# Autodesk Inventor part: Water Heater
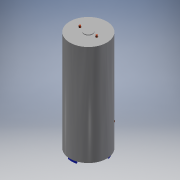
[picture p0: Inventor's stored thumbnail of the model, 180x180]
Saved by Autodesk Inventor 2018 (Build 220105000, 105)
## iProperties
flow_configuration: 1
height: 0 in
loss_method: 0
radius: 2.500 in
shape: 1 ul
width: 0 in
allow_slope_adjustment: 0
flow_configuration2: 1
flow_direction: 2
radius: 0.500 in
shape: 0 ul
Created: 2006-02
Part Number: Water Heater
Document SubType Name: Modeling
Designer: Autodesk, Inc.
Description: BODY - WATER HEATER, 45 GAL
Mass: 2.9406e+06 g
Surface Area: 32761.1 cm^2
Volume: 374598 cm^3
Density: 7.85 g/cm^3
Material: Galvanized Steel
Appearance: Steel
Title: BODY - WATER HEATER, 45 GAL
Author: Autodesk, Inc.
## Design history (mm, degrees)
sketch "Sketch1"
  geometry: C1 r 279.4 at (0, 0)
  constraints: 1 centre point
  dimensions: "d0" = 558.8 diameter of C1
extrude "Extrusion1" new body sketch "Sketch1" distance "d1" = 1524; taper "d2" = 0 deg
workplane "Work Plane2"
sketch "Sketch2"
  geometry: C1 r 241.3 at (0, 0); C2 r 63.5 at (0, 0); C3 r 279.4 at (0, 0) reference
  constraints: 2 centre point, 1 coincident
  dimensions: "d4" = 127 diameter of C2
extrude "Extrusion2" join sketch "Sketch2" distance "d5" = 9.525; taper "d6" = 0 deg
workplane "Work Plane1"
sketch "Sketch3"
  geometry: C1 r 241.3 at (0, 0); C2 r 18.528 at (-127, 0); C3 r 18.528 at (127, 0); C4 r 63.5 at (0, 0) reference; C5 r 279.4 at (0, 0) reference
  constraints: 3 centre point, 2 horizontal alignment, 1 equal radius
  dimensions: "d8" = 127 distance of C2.centre C1.centre; "d9" = 254 distance of C2.centre C3.centre (= 2 x d8); "d10" = 37.05617 diameter of C2
extrude "Extrusion3" cut sketch "Sketch3" distance "d11" = 9.525; taper "d12" = 0 deg
workplane "Work Plane3"
sketch "Sketch4"
  geometry: C1 r 15.875 at (0, 1340.887)
  constraints: 1 centre point
  dimensions: "d13" = 31.75 diameter of C1
extrude "Extrusion4" cut sketch "Sketch4" distance "d14" = 9.525; taper "d15" = 0 deg
sketch "Sketch5"
  geometry: C1 r 18.528 at (0, 0) reference; C2 r 12.7 at (0, 0); 1 further point
  constraints: 1 centre point, 1 coincident
  dimensions: "d16" = 25.4 diameter of C2
extrude "Extrusion5" new body sketch "Sketch5" distance "d17" = 34.925; taper "d18" = 0 deg
pattern_linear "Rectangular Pattern1" dims "d21" = 254
sketch "Sketch6"
  geometry: L1 (0, 0)-(0, 262.412); L2 (60.612, 226.208)-(65.543, 244.609); L3 (-60.612, 226.208)-(-65.543, 244.609); C1 r 279.4 at (0, 0) reference; A1 r 234.188 centre (0, 0) between (60.612, 226.208) and (-60.612, 226.208); A2 r 253.238 centre (0, 0) between (65.543, 244.609) and (-65.543, 244.609)
  constraints: 6 end point, 4 point on circle, 2 centre point, 2 coincident, 2 point on line, 1 vertical
  dimensions: "d22" = 30 deg angle of L2 L3; "d23" = 15 deg angle of L2 L1; "d24" = 19.05 radial gap between concentric circles of A2 A1; "d25" = 468.376 diameter of A1
extrude "Extrusion6" new body sketch "Sketch6" distance "d26" = 50.8; taper "d27" = 0 deg
pattern_circular "Circular Pattern1" dims angle "d29" = 360 deg
sketch "Sketch7"
  geometry: C1 r 15.875 at (0, 0) reference; C2 r 12.7 at (0, 0); 1 further point
  constraints: 1 centre point, 1 coincident
  dimensions: "d31" = 25.4 diameter of C2
extrude "Extrusion7" new body sketch "Sketch7" distance "d32" = 34.925; taper "d33" = 0 deg
workplane "Work Plane4"
sketch "Sketch8"
  geometry: L1 (-38.1, 279.4)-(38.1, 279.4); L2 (38.1, 279.4)-(38.1, 203.2); L3 (-38.1, 203.2)-(-38.1, 279.4); L4 (-279.4, 0)-(279.4, 0) reference; L5 (38.1, 203.2)-(14.028, 203.2); L6 (-14.028, 203.2)-(-38.1, 203.2); L7 (0, -55.88)-(0, 335.28) reference; A1 r 19.355 centre (0, 216.535) between (-14.028, 203.2) and (14.028, 203.2); 3 further points
  constraints: 10 end point, 3 parallel, 2 point on circle, 1 centre point, 1 coincident, 1 collinear, 1 horizontal, 1 perpendicular, 1 point on line, 1 vertical alignment
  dimensions: "d35" = 76.2 distance between parallel lines of L2 L3; "d36" = 76.2 distance of L3.start L1.start; "d37" = 38.1 distance from line of L2 point (0, 241.3); "d39" = 241.3 distance from line of L4 point (0, 241.3); "d40" = 24.765 distance of point (0, 241.3) point (0, 216.535); "d41" = 38.7096 diameter of A1; "d42" = 38.1 distance from line of L6 point (0, 241.3)
extrude "Extrusion8" new body sketch "Sketch8" distance "d43" = 50.8; taper "d44" = 0 deg
sketch "Sketch9"
  geometry: L1 (0, 76.2)-(0, 0) reference; L2 (0, 76.2)-(-50.8, 76.2) reference; C1 r 12.7 at (-25.4, 38.1); 2 further points
  constraints: 1 centre point, 1 coincident
  dimensions: "d45" = 25.4 diameter of C1; "d46" = 38.1 distance from line of L2 point (-25.4, 38.1); "d47" = 25.4 distance from line of L1 point (-25.4, 38.1)
extrude "Extrusion9" new body sketch "Sketch9" distance "d48" = 50.8; taper "d49" = 0 deg
body "Solid1"
body "Solid2"
feature "Pattern of Solid2:1"
body "Solid3"
body "Solid4"
body "Solid5"
body "Solid6"
body "Solid7"
other parameters: "d34" = -330.2, "d38" = 38.1
